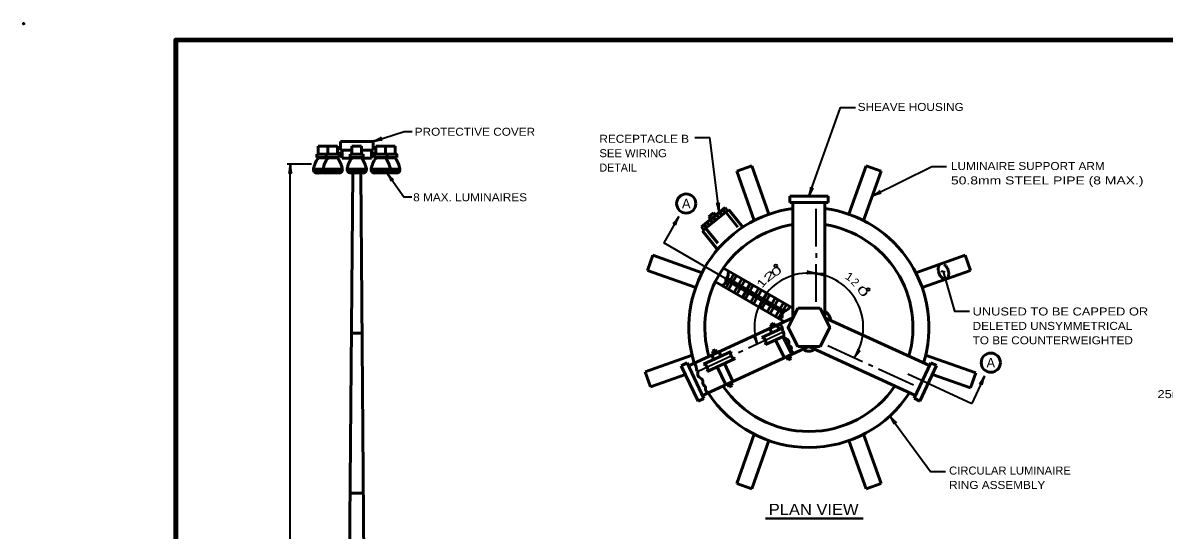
# Model space of a CAD drawing. Extents: x -24 to 689, y -7 to 446.
# Drawn here: x -24.1 to 332.4, y 287.5 to 446 of the extents above; entities that cross this region are included whole.
import ezdxf
from ezdxf.enums import TextEntityAlignment as Align

# ---------------------------------------------------------------- set-up
doc = ezdxf.new("R2010")
doc.units = 0
doc.header["$PDMODE"] = 32
doc.header["$PDSIZE"] = 0.5
doc.linetypes.add('LONG_DASHED', pattern=[7.5, 6, -1.5])
doc.layers.add('1', color=7, linetype='Continuous', lineweight=35)

msp = doc.modelspace()

# ---------------------------------------------------------------- linework, layer by layer
at = {"layer": '1'}
for p, q in [((185.76, 410.106), (190.424, 410.106)), ((193.344, 386.91), (190.424, 410.106)), ((66.113, 401.804), (58.446, 401.804)), ((59.446, 148.054), (59.446, 401.804)), ((180.807, 385.484), (176.057, 377.257)), ((192.115, 384.121), (191.329, 385.093)), ((192.504, 384.436), (191.718, 385.407)), ((193.087, 384.908), (192.3, 385.879)), ((193.476, 385.223), (192.689, 386.194)), ((194.059, 385.695), (193.272, 386.666)), ((194.447, 386.009), (193.661, 386.981)), ((195.03, 386.481), (194.243, 387.453)), ((195.419, 386.796), (194.632, 387.768)), ((223.666, 376.071), (223.666, 387.821)), ((189.202, 381.762), (188.415, 382.733)), ((189.59, 382.076), (188.803, 383.048)), ((190.173, 382.548), (189.386, 383.52)), ((190.561, 382.863), (189.775, 383.834)), ((191.144, 383.335), (190.357, 384.306)), ((191.533, 383.649), (190.746, 384.621)), ((195.11, 366.257), (176.057, 377.257)), ((223.666, 374.071), (223.666, 372.571)), ((223.666, 358.821), (223.666, 370.571)), ((202.587, 344.433), (213.39, 349.402)), ((199.407, 342.971), (200.77, 343.597)), ((227.313, 345.146), (238.179, 340.172)), ((186.787, 337.166), (197.59, 342.135)), ((239.997, 339.339), (241.361, 338.715)), ((243.179, 337.882), (254.046, 332.909)), ((252.346, 336.354), (272.27, 327.024)), ((276.299, 335.628), (272.27, 327.024))]:
    msp.add_line(p, q, dxfattribs=at)
at = {"layer": '1', "lineweight": 53}
for p, q in [((68.196, 407.429), (71.196, 407.429)), ((68.196, 407.429), (68.196, 404.929)), ((71.196, 407.429), (74.196, 407.429)), ((71.196, 407.429), (71.196, 404.929)), ((71.196, 407.429), (71.196, 404.929)), ((74.196, 407.429), (74.196, 404.929)), ((75.106, 406.179), (75.106, 408.929)), ((78.696, 407.429), (81.696, 407.429)), ((78.696, 407.429), (78.696, 404.929)), ((81.696, 407.429), (81.696, 404.929)), ((86.196, 407.429), (89.196, 407.429)), ((86.196, 407.429), (86.196, 404.929)), ((89.196, 407.429), (89.196, 404.929)), ((89.196, 407.429), (92.196, 407.429)), ((89.196, 407.429), (89.196, 404.929)), ((92.196, 407.429), (92.196, 404.929)), ((67.696, 404.929), (71.696, 404.929)), ((67.696, 404.929), (67.696, 403.929)), ((67.696, 403.929), (71.696, 403.929)), ((68.196, 403.804), (71.196, 403.804)), ((70.696, 404.929), (74.696, 404.929)), ((70.696, 404.929), (70.696, 403.929)), ((70.696, 403.929), (74.696, 403.929)), ((71.196, 403.804), (74.196, 403.804)), ((74.696, 404.929), (74.696, 403.929)), ((75.106, 406.179), (78.696, 406.179)), ((75.606, 403.679), (75.606, 406.179)), ((75.606, 403.679), (78.606, 403.679)), ((78.196, 404.929), (82.196, 404.929)), ((78.196, 404.929), (78.196, 403.929)), ((78.196, 403.929), (82.196, 403.929)), ((78.696, 403.804), (81.696, 403.804)), ((85.285, 406.179), (81.696, 406.179)), ((81.785, 403.679), (84.785, 403.679)), ((82.196, 404.929), (82.196, 403.929)), ((84.785, 403.679), (84.785, 406.179)), ((85.696, 404.929), (89.696, 404.929)), ((85.696, 404.929), (85.696, 403.929)), ((85.696, 403.929), (89.696, 403.929)), ((86.196, 403.804), (89.196, 403.804)), ((88.696, 403.929), (92.696, 403.929)), ((89.196, 403.804), (92.196, 403.804)), ((89.696, 404.929), (89.696, 403.929)), ((66.321, 400.304), (72.196, 400.304)), ((67.884, 400.304), (68.38, 399.064)), ((68.696, 400.304), (69.196, 399.054)), ((69.696, 400.304), (75.196, 400.304)), ((70.196, 400.304), (70.583, 399.066)), ((70.884, 400.304), (71.38, 399.064)), ((71.696, 400.304), (72.196, 399.054)), ((72.196, 400.304), (73.196, 400.304)), ((72.696, 400.304), (72.696, 399.054)), ((73.696, 400.304), (73.196, 399.054)), ((74.455, 400.304), (73.956, 399.056)), ((75.196, 400.304), (74.808, 399.066)), ((75.196, 400.304), (76.071, 400.304)), ((76.821, 400.304), (77.696, 400.304)), ((77.696, 400.304), (78.083, 399.066)), ((77.696, 400.304), (82.696, 400.304)), ((78.384, 400.304), (78.88, 399.064)), ((79.196, 400.304), (79.696, 399.054)), ((80.196, 400.304), (80.196, 399.054)), ((81.196, 400.304), (80.696, 399.054)), ((81.955, 400.304), (81.456, 399.056)), ((82.696, 400.304), (82.308, 399.066)), ((82.696, 400.304), (83.571, 400.304)), ((84.321, 400.304), (85.196, 400.304)), ((85.196, 400.304), (85.583, 399.066)), ((85.196, 400.304), (90.696, 400.304)), ((85.884, 400.304), (86.358, 399.118)), ((86.696, 400.304), (87.196, 399.054)), ((87.196, 400.304), (88.196, 400.304)), ((87.696, 400.304), (87.696, 399.054)), ((88.696, 400.304), (88.196, 399.054)), ((88.196, 400.304), (93.196, 400.304)), ((89.455, 400.304), (88.988, 399.137)), ((90.196, 400.304), (89.808, 399.066)), ((91.696, 400.304), (91.196, 399.054)), ((92.455, 400.304), (91.988, 399.137)), ((93.196, 400.304), (92.808, 399.066)), ((93.196, 400.304), (94.071, 400.304)), ((198.868, 399.594), (203.582, 401.261)), ((198.868, 399.594), (204.313, 384.194)), ((203.582, 401.261), (208.916, 386.176)), ((239.249, 401.261), (233.915, 386.176)), ((243.963, 399.594), (238.518, 384.194)), ((239.249, 401.261), (243.963, 399.594)), ((70.583, 399.066), (74.696, 399.054)), ((78.946, 399.063), (76.946, 149.054)), ((78.083, 399.066), (82.196, 399.054)), ((81.446, 399.056), (83.446, 149.054)), ((85.583, 399.066), (89.696, 399.054)), ((88.583, 399.066), (92.696, 399.054)), ((215.415, 391.821), (227.415, 391.821)), ((215.415, 391.821), (215.416, 389.821)), ((215.416, 389.821), (227.415, 389.821)), ((226.416, 353.821), (226.416, 389.821)), ((227.415, 391.821), (227.415, 389.821)), ((195.215, 388.24), (187.832, 382.261)), ((196.39, 387.583), (188.23, 380.975)), ((191.671, 386.656), (190.117, 385.398)), ((190.746, 384.621), (190.117, 385.398)), ((192.3, 385.879), (191.671, 386.656)), ((196.002, 387.268), (195.215, 388.24)), ((199.195, 382.133), (195.419, 386.796)), ((200.796, 382.143), (196.39, 387.583)), ((188.619, 381.29), (187.832, 382.261)), ((192.977, 377.099), (189.201, 381.762)), ((192.914, 375.191), (188.23, 380.975)), ((170.975, 368.654), (172.642, 373.368)), ((172.642, 373.368), (188.042, 367.923)), ((254.788, 367.923), (270.189, 373.368)), ((270.189, 373.368), (271.856, 368.654)), ((170.975, 368.654), (186.06, 363.321)), ((216.416, 356.821), (194.715, 369.35)), ((197.92, 367.499), (195.439, 363.202)), ((256.771, 363.321), (271.856, 368.654)), ((213.784, 352.61), (192.205, 365.069)), ((198.786, 366.999), (196.305, 362.702)), ((200.518, 365.999), (198.037, 361.702)), ((201.384, 365.499), (198.903, 361.202)), ((203.116, 364.499), (200.635, 360.202)), ((203.982, 363.999), (201.501, 359.702)), ((205.714, 362.999), (203.233, 358.702)), ((206.58, 362.499), (204.099, 358.202)), ((208.312, 361.499), (205.831, 357.202)), ((209.178, 360.999), (206.697, 356.702)), ((210.91, 359.999), (208.429, 355.702)), ((211.776, 359.499), (209.295, 355.202)), ((213.508, 358.499), (211.027, 354.202)), ((214.374, 357.999), (211.893, 353.701)), ((217.916, 356.821), (224.916, 356.821)), ((183.799, 338.819), (216.416, 353.821)), ((226.416, 353.821), (259.051, 338.882)), ((206.695, 347.699), (213.034, 350.614)), ((209.241, 350.431), (209.875, 349.162)), ((209.464, 351.661), (210.359, 352.108)), ((209.464, 351.661), (209.886, 350.817)), ((210.359, 352.108), (210.795, 351.236)), ((211.477, 351.549), (212.148, 350.207)), ((78.546, 349.054), (81.846, 349.054)), ((207.814, 345.462), (213.548, 348.099)), ((210.994, 346.924), (213.834, 341.244)), ((213.266, 347.97), (216.07, 342.362)), ((188.169, 329.529), (221.415, 344.821)), ((188.526, 339.342), (197.157, 343.312)), ((191.317, 343.394), (192.221, 343.819)), ((191.317, 343.394), (191.749, 342.475)), ((192.221, 343.819), (192.657, 342.893)), ((193.326, 343.234), (193.977, 341.849)), ((217.916, 344.821), (224.915, 344.821)), ((221.415, 344.821), (254.698, 329.586)), ((257.788, 342.204), (273.505, 336.647)), ((170.273, 336.982), (184.928, 342.163)), ((181.564, 338.872), (183.374, 339.724)), ((181.564, 338.872), (186.785, 327.773)), ((183.374, 339.724), (188.594, 328.624)), ((189.59, 337.079), (198.337, 341.103)), ((191.064, 342.17), (191.706, 340.804)), ((195.041, 339.587), (197.695, 333.944)), ((214.479, 341.631), (214.952, 340.685)), ((215.846, 341.132), (214.952, 340.685)), ((215.388, 342.049), (215.846, 341.132)), ((259.475, 339.788), (254.274, 328.68)), ((261.287, 338.939), (256.085, 327.832)), ((259.475, 339.788), (261.287, 338.939)), ((171.94, 332.268), (170.273, 336.982)), ((171.94, 332.268), (182.855, 336.127)), ((192.77, 338.542), (195.433, 332.88)), ((259.971, 336.129), (271.838, 331.933)), ((273.505, 336.647), (271.838, 331.933)), ((196.118, 333.185), (196.538, 332.294)), ((197.442, 332.72), (196.538, 332.294)), ((197.027, 333.603), (197.442, 332.72)), ((186.785, 327.773), (188.594, 328.624)), ((254.274, 328.68), (256.085, 327.832)), ((204.313, 317.448), (198.868, 302.047)), ((238.518, 317.448), (243.963, 302.047)), ((208.916, 315.465), (203.582, 300.38)), ((233.915, 315.466), (239.249, 300.381)), ((203.582, 300.38), (198.868, 302.047)), ((243.963, 302.047), (239.249, 300.381)), ((78.146, 299.054), (82.246, 299.054))]:
    msp.add_line(p, q, dxfattribs=at)
at = {"layer": '1', "lineweight": 106}
for p, q in [((75.606, 404.929), (74.696, 404.929)), ((84.785, 404.929), (85.696, 404.929))]:
    msp.add_line(p, q, dxfattribs=at)
at = {"layer": '1', "lineweight": 200}
msp.add_line((195.631, 365.956), (213.41, 355.691), dxfattribs=at)
at = {"layer": '1', "lineweight": 40}
msp.add_line((207.899, 291.106), (238.388, 291.106), dxfattribs=at)
at = {"layer": '1', "lineweight": 158}
msp.add_lwpolyline([(683.413, 440.647), (23.663, 440.564), (23.747, 2.23)], dxfattribs=at)
at = {"layer": '1'}
for points in [[(221.415, 391.821), (231.273, 419.49), (235.936, 419.49)], [(85.285, 408.929), (95.027, 412.036), (97.483, 412.036)], [(241.24, 391.894), (259.769, 401.117), (264.432, 401.117)], [(89.696, 399.054), (94.903, 391.61), (97.451, 391.61)], [(263.365, 368.261), (266.858, 355.942), (271.521, 355.942)], [(246.702, 323.129), (259.408, 305.817), (264.071, 305.817)]]:
    msp.add_lwpolyline(points, dxfattribs=at)
at = {"layer": '1', "lineweight": 53}
for points in [[(85.285, 406.179), (85.285, 408.929), (75.106, 408.929)], [(88.696, 404.929), (92.696, 404.929), (92.696, 403.929)], [(67.196, 400.304), (67.583, 399.066), (71.696, 399.054)], [(216.416, 353.821), (216.416, 387.986), (216.416, 389.821)], [(217.916, 356.821), (214.916, 350.821), (217.916, 344.821)], [(224.915, 344.821), (227.915, 350.821), (224.916, 356.821)]]:
    msp.add_lwpolyline(points, dxfattribs=at)
for centre in [(183.109, 389.517), (278.22, 339.813)]:
    msp.add_circle(centre, 3, dxfattribs=at)
at = {"layer": '1'}
for centre in [(211.087, 370.039), (239.939, 362.669)]:
    msp.add_circle(centre, 0.45, dxfattribs=at)
at = {"layer": '1', "lineweight": 53}
for centre, radius, start, end in [((75.102, 398.772), 8.545, 143.92712, 169.6757), ((78.102, 398.772), 8.545, 143.92712, 169.6757), ((67.289, 398.772), 8.545, 10.3243, 36.07288), ((85.602, 398.772), 8.545, 143.92712, 169.6757), ((74.789, 398.772), 8.545, 10.3243, 36.07288), ((93.102, 398.772), 8.545, 143.92712, 169.6757), ((82.289, 398.772), 8.545, 10.3243, 36.07288), ((85.289, 398.772), 8.545, 10.3243, 36.07288), ((67.758, 400.128), 1.077, 170.6394, 266.68021), ((70.758, 400.128), 1.077, 170.6394, 266.68021), ((74.633, 400.128), 1.077, 273.31979, 9.3606), ((78.258, 400.128), 1.077, 170.6394, 260.64075), ((82.133, 400.128), 1.077, 273.31979, 9.3606), ((85.758, 400.128), 1.077, 170.6394, 266.68021), ((89.633, 400.128), 1.077, 273.31979, 9.3606), ((92.633, 400.128), 1.077, 273.31979, 9.3606), ((221.415, 350.821), 37.5, 97.66187, 197.32332), ((221.415, 350.821), 37.5, 342.77204, 82.33736), ((221.415, 350.821), 32.5, 98.84944, 196.18056), ((221.415, 350.821), 32.5, 343.91337, 81.14967), ((224.68, 352.706), 3.565, 4.53272, 60.86921), ((206.501, 346.226), 1.486, 327.89377, 82.48428), ((198.452, 342.584), 1.486, 150.66912, 265.55469), ((221.414, 346.606), 3.188, 235.2883, 304.81151), ((188.332, 337.869), 1.486, 327.89377, 82.48428), ((221.415, 350.821), 32.5, 214.35563, 325.74061), ((221.415, 350.821), 37.5, 213.05829, 327.03907)]:
    msp.add_arc(centre, radius, start, end, dxfattribs=at)
at = {"layer": '1'}
for centre, radius, start, end in [((221.415, 350.821), 17, 82.39357, 197.72393), ((221.415, 350.821), 17, 326.24589, 82.39357), ((263.122, 367.999), 0.357, 47.242, 165.78449), ((263.607, 368.523), 0.357, 227.242, 345.78449)]:
    msp.add_arc(centre, radius, start, end, dxfattribs=at)
at = {"layer": '1', "lineweight": 40}
for centre, major_axis, ratio, start_param, end_param in [((86.241, 409.523), (-1.654, -0.691), 0.122415, 0.8963533, 3.1415927), ((86.417, 409.067), (-1.727, -0.366), 0.07063, 3.1407148, 5.41811), ((59.234, 400.683), (0.176, 1.756), 0.07063, 3.1407148, 5.41811), ((59.722, 400.712), (-0.156, 1.786), 0.122415, 0.8963533, 3.1415927), ((90.165, 398.014), (0.863, -1.54), 0.07063, 6.2823074, 8.5597026), ((90.548, 398.318), (-1.151, 1.374), 0.122415, 0.8963533, 3.1415927), ((221.521, 392.941), (-0.452, -1.735), 0.122415, 0.8963533, 3.1415927), ((221.521, 392.941), (-0.452, -1.735), 0.122415, 0.8963533, 3.1415927), ((221.991, 392.805), (-0.755, -1.596), 0.07063, 3.1407148, 5.41811), ((221.991, 392.805), (-0.755, -1.596), 0.07063, 3.1407148, 5.41811), ((242.094, 392.628), (-1.529, -0.935), 0.122415, 0.8963533, 3.1415927), ((242.094, 392.628), (-1.529, -0.935), 0.122415, 0.8963533, 3.1415927), ((242.338, 392.204), (1.651, 0.625), 0.07063, 6.2823074, 8.5597026), ((242.338, 392.204), (1.651, 0.625), 0.07063, 6.2823074, 8.5597026), ((192.933, 387.958), (0.378, -1.752), 0.122415, 0.8963533, 3.1415927), ((192.933, 387.958), (0.378, -1.752), 0.122415, 0.8963533, 3.1415927), ((193.414, 388.048), (-0.045, 1.765), 0.07063, 6.2823074, 8.5597026), ((193.414, 388.048), (-0.045, 1.765), 0.07063, 6.2823074, 8.5597026), ((180.064, 384.619), (1.03, 1.433), 0.07063, 3.1407148, 5.41811), ((180.064, 384.619), (1.03, 1.433), 0.07063, 3.1407148, 5.41811), ((180.501, 384.401), (0.758, 1.625), 0.122415, 0.8963533, 3.1415927), ((180.501, 384.401), (0.758, 1.625), 0.122415, 0.8963533, 3.1415927), ((222.547, 367.542), (1.791, -0.082), 0.122415, 0.8963533, 3.1415927), ((222.547, 367.542), (1.791, -0.082), 0.122415, 0.8963533, 3.1415927), ((222.583, 368.029), (-1.718, 0.407), 0.07063, 6.2823074, 8.5597026), ((222.583, 368.029), (-1.718, 0.407), 0.07063, 6.2823074, 8.5597026), ((224.748, 367.313), (1.718, -0.407), 0.07063, 6.2823074, 8.5597026), ((224.748, 367.313), (1.718, -0.407), 0.07063, 6.2823074, 8.5597026), ((224.784, 367.801), (-1.791, 0.082), 0.122415, 0.8963533, 3.1415927), ((224.784, 367.801), (-1.791, 0.082), 0.122415, 0.8963533, 3.1415927), ((204.627, 346.601), (0.692, -1.653), 0.122415, 0.8963533, 3.1415927), ((205.083, 346.777), (0.367, -1.727), 0.07063, 3.1407148, 5.41811), ((235.926, 342.436), (-0.862, -1.571), 0.122415, 0.8963533, 3.1415927), ((236.348, 342.189), (1.122, 1.363), 0.07063, 6.2823074, 8.5597026), ((275.632, 334.703), (0.904, 1.516), 0.07063, 3.1407148, 5.41811), ((276.086, 334.522), (0.616, 1.683), 0.122415, 0.8963533, 3.1415927), ((247.194, 322.101), (-0.898, 1.52), 0.07063, 3.1407148, 5.41811), ((247.57, 322.413), (-1.182, 1.347), 0.122415, 0.8963533, 3.1415927)]:
    msp.add_ellipse(centre, major_axis=major_axis, ratio=ratio, start_param=start_param, end_param=end_param, dxfattribs=at)
at = {"layer": '1', "linetype": 'LONG_DASHED', "lineweight": 53}
msp.add_ellipse((263.44, 368.331), major_axis=(0.833, -2.357), ratio=0.599999, dxfattribs=at)
at = {"layer": '1', "lineweight": 53}
for points in [[(196.447, 368.35), (196.234, 367.703), (196.007, 366.626), (195.469, 365.917), (195.469, 365.067), (195.044, 364.472), (194.534, 363.962), (194.803, 363.569)], [(215.549, 357.321), (214.902, 356.51), (213.684, 355.773), (213.06, 355.065), (213.089, 354.158), (212.052, 353.61)], [(212.457, 351.952), (213.168, 350.303), (213.25, 349.729), (213.537, 349.237), (213.578, 348.007), (215.012, 346.737), (215.422, 344.974), (215.832, 344.728), (215.914, 343.908), (216.827, 342.662)], [(185.616, 339.655), (186.327, 338.005), (186.409, 337.432), (186.696, 336.94), (186.737, 335.71), (188.171, 334.439), (188.581, 332.677), (188.991, 332.431), (189.073, 331.611), (189.986, 330.365)]]:
    msp.add_spline(points, degree=3, dxfattribs=at)
at = {"layer": '1'}
for p in [(-23.837, 445.73), (68.196, 399.054)]:
    msp.add_point(p, dxfattribs=at)

# ---------------------------------------------------------------- texts
for s, height, width, p in [('SHEAVE HOUSING', 2.5, 1.1, (253.212, 418.453)), ('PROTECTIVE COVER', 2.5, 1.1, (117.103, 410.703)), ('8 MAX. LUMINAIRES', 2.5, 1.1, (115.612, 390.236)), ('25mm FLEXIBLE CONDUIT', 2.5, 1.2, (355.48, 328.73)), ('PLAN VIEW', 3.5, 1.1, (222.905, 292.209))]:
    msp.add_text(s, height=height, dxfattribs=dict(at, width=width)).set_placement(p, align=Align.CENTER)
for s, width, p in [('RECEPTACLE B', 1.1, (155.982, 408.501)), ('SEE WIRING', 1.05, (155.982, 404.001)), ('LUMINAIRE SUPPORT ARM', 1.1, (265.777, 399.993)), ('50.8mm STEEL PIPE (8 MAX.)', 1.3, (265.777, 395.493)), ('UNUSED TO BE CAPPED OR', 1.2, (272.543, 354.552)), ('DELETED UNSYMMETRICAL', 1.1, (272.543, 350.052)), ('TO BE COUNTERWEIGHTED', 1.1, (272.543, 345.552)), ('CIRCULAR LUMINAIRE', 1.05, (265.197, 304.858)), ('RING ASSEMBLY', 1.1, (265.197, 300.358))]:
    msp.add_text(s, height=2.5, dxfattribs=dict(at, width=width)).set_placement(p)
msp.add_text('DETAIL', height=2.5, dxfattribs=at).set_placement((155.982, 399.501))
for p in [(183.109, 388.017), (278.22, 338.313)]:
    msp.add_text('A', height=3, dxfattribs=at).set_placement(p, align=Align.CENTER)
for s, rotation, width, p in [('2', 39.009, 1.95, (209.837, 365.861)), ('0', 32.793, 1.75, (211.911, 367.27)), ('1', 326.369, 1.2, (233.383, 365.649)), ('1', 51.44, 1.4, (207.6, 363.931)), ('0', 307.723, 1.9, (237.255, 361.357))]:
    msp.add_text(s, height=2.5, rotation=rotation, dxfattribs=dict(at, width=width)).set_placement(p, align=Align.CENTER)
msp.add_text('2', height=2.5, rotation=313.938, dxfattribs=at).set_placement((234.972, 364.099), align=Align.CENTER)

doc.saveas('drawing.dxf')
